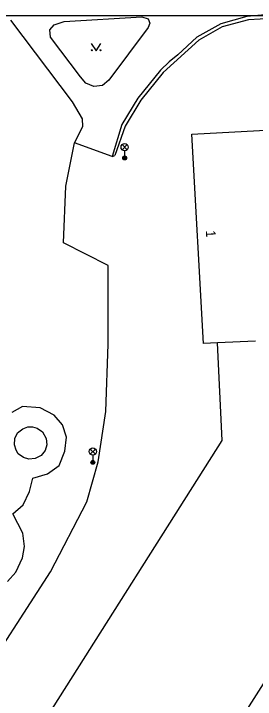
# Model space of a CAD drawing. Extents: x -598341 to -594502, y -1162301 to -1161406.
# Drawn here: x -594835.2 to -594810.1, y -1161499.6 to -1161428.3 of the extents above; entities that cross this region are included whole.
import ezdxf

# ---------------------------------------------------------------- set-up
doc = ezdxf.new("R2010")
doc.units = 0
for name, color, linetype in [('OKRAJ', 7, 'Continuous'), ('Vrstva 11', 7, 'Continuous'), ('Vrstva 33', 7, 'Continuous'), ('Vrstva 36', 7, 'Continuous'), ('Vrstva 46', 7, 'Continuous'), ('Vrstva 5', 7, 'Continuous')]:
    doc.layers.add(name, color=color, linetype=linetype)

msp = doc.modelspace()

# ---------------------------------------------------------------- linework, layer by layer
at = {"layer": 'OKRAJ'}
msp.add_line((-594937.093, -1161428.479), (-594533.893, -1161428.479), dxfattribs=at)
at = {"layer": 'Vrstva 11'}
for p, q in [((-594810.79, -1161428.95), (-594813.53, -1161429.67)), ((-594806.56, -1161428.67), (-594810.79, -1161428.95)), ((-594813.53, -1161429.67), (-594815.96, -1161431.07)), ((-594815.96, -1161431.07), (-594819.66, -1161434.41)), ((-594818.16, -1161432.59), (-594819.04, -1161433.31)), ((-594819.66, -1161434.41), (-594821.98, -1161437.32)), ((-594821.98, -1161437.32), (-594823.61, -1161440)), ((-594828.05, -1161440.05), (-594828.89, -1161441.76)), ((-594823.61, -1161440), (-594824.68, -1161443.07)), ((-594824.96, -1161443.15), (-594828.89, -1161441.76)), ((-594824.96, -1161443.15), (-594824.68, -1161443.07))]:
    msp.add_line(p, q, dxfattribs=at)
for points in [[(-594807.92, -1161428.31), (-594810.97, -1161428.59), (-594813.68, -1161429.35), (-594816.17, -1161430.76), (-594818.16, -1161432.59)], [(-594835.52, -1161428.98), (-594829.13, -1161437.48), (-594828.09, -1161439.24), (-594828.05, -1161440.05)], [(-594831.37, -1161430.76), (-594831.43, -1161430), (-594830.99, -1161429.48), (-594829.94, -1161429.12), (-594821.9, -1161428.62), (-594821.23, -1161428.83), (-594821.05, -1161429.28), (-594821.24, -1161429.73), (-594823.27, -1161432.48), (-594825.3, -1161435.22), (-594825.96, -1161435.77), (-594826.86, -1161435.88), (-594827.69, -1161435.54), (-594828.27, -1161434.89), (-594831.37, -1161430.76)], [(-594819.04, -1161433.31), (-594819.93, -1161434.18), (-594822.29, -1161437.08), (-594823.98, -1161439.85), (-594824.96, -1161443.15)], [(-594859.45, -1161527.51), (-594849.78, -1161510.3), (-594846.08, -1161505.6), (-594841.96, -1161501.57), (-594839.4, -1161498.78), (-594831.38, -1161486.39), (-594827.61, -1161479.09), (-594826.43, -1161474.93), (-594825.64, -1161469.7), (-594825.37, -1161462.68), (-594825.38, -1161454.5), (-594830.03, -1161452.15), (-594829.78, -1161446.24), (-594828.89, -1161441.76)], [(-594835.83, -1161487.39), (-594834.99, -1161486.43), (-594834.29, -1161484.93), (-594834.06, -1161483.75), (-594834.24, -1161482.37), (-594835.3, -1161480.34), (-594834.2, -1161479.4), (-594833.57, -1161478.01), (-594833.2, -1161476.62), (-594831.7, -1161476.19), (-594830.46, -1161475.33), (-594829.88, -1161473.83), (-594829.72, -1161472.38), (-594830.14, -1161471.09), (-594831, -1161470.07), (-594832.45, -1161469.32), (-594834.27, -1161469.16), (-594835.4, -1161469.8)], [(-594834.17, -1161474.49), (-594834.72, -1161474.11), (-594834.93, -1161473.73), (-594835.1, -1161473.15), (-594835.07, -1161472.49), (-594834.81, -1161471.93), (-594834.25, -1161471.5), (-594833.72, -1161471.29), (-594833.25, -1161471.3), (-594832.75, -1161471.44)], [(-594832.75, -1161471.44), (-594832.22, -1161471.83), (-594831.82, -1161472.49), (-594831.75, -1161473.17), (-594831.94, -1161473.75), (-594832.36, -1161474.27), (-594832.97, -1161474.59), (-594833.61, -1161474.66), (-594834.17, -1161474.49)]]:
    msp.add_lwpolyline(points, dxfattribs=at)
at = {"layer": 'Vrstva 33'}
for p, q in [((-594823.935, -1161442.46), (-594823.405, -1161441.93)), ((-594823.935, -1161441.93), (-594823.405, -1161442.46)), ((-594823.67, -1161442.57), (-594823.67, -1161443.32)), ((-594827.245, -1161474.13), (-594826.715, -1161473.6)), ((-594827.245, -1161473.6), (-594826.715, -1161474.13)), ((-594826.98, -1161474.24), (-594826.98, -1161474.99))]:
    msp.add_line(p, q, dxfattribs=at)
for centre, radius in [((-594823.67, -1161442.195), 0.375), ((-594823.67, -1161443.32), 0.2), ((-594823.67, -1161443.32), 0.145), ((-594823.67, -1161443.32), 0.0876), ((-594826.98, -1161473.865), 0.375), ((-594826.98, -1161474.99), 0.2), ((-594826.98, -1161474.99), 0.145), ((-594826.98, -1161474.99), 0.0876)]:
    msp.add_circle(centre, radius, dxfattribs=at)
at = {"layer": 'Vrstva 36'}
msp.add_lwpolyline([(-594827.14, -1161431.42), (-594826.64, -1161432.17), (-594826.14, -1161431.42)], dxfattribs=at)
for centre in [(-594827.091, -1161432.119), (-594826.191, -1161432.119)]:
    msp.add_circle(centre, 0.05, dxfattribs=at)
at = {"layer": 'Vrstva 5'}
for p, q in [((-594816.7, -1161440.84), (-594800.62, -1161439.94)), ((-594815.48, -1161462.62), (-594816.7, -1161440.84)), ((-594814.03, -1161462.55), (-594815.48, -1161462.62)), ((-594810.07, -1161462.37), (-594814.03, -1161462.55)), ((-594813.52, -1161472.72), (-594814.03, -1161462.55)), ((-594839.26, -1161513.37), (-594813.52, -1161472.72)), ((-594799.12, -1161481.9), (-594824.8, -1161522.6))]:
    msp.add_line(p, q, dxfattribs=at)

# ---------------------------------------------------------------- texts
at = {"layer": 'Vrstva 46'}
msp.add_text('1', height=1, rotation=273.19, dxfattribs=at).set_placement((-594815.23, -1161450.87))

doc.saveas('drawing.dxf')
